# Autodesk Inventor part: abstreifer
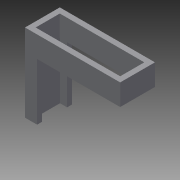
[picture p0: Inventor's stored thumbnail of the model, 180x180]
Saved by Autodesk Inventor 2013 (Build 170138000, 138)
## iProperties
Created: 2012-11
Part Number: abstreifer
Material: Allgemein
Document SubType Name: Modeling
Designer: otto
Density: 1 g/cm^3
Mass: 571.291 g
Surface Area: 1347.68 cm^2
Volume: 571.291 cm^3
Author: otto
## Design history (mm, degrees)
sketch "Skizze1"
  geometry: L1 (-119, -34)-(119, -34) reference; L2 (119, -34)-(119, 34) reference; L3 (119, 34)-(-119, 34) reference; L4 (-119, 34)-(-119, -34) reference; L5 (-129, 44)-(129, 44); L6 (129, 44)-(129, -44); L7 (129, -44)-(-129, -44); L8 (-129, -44)-(-129, 44); 1 further point
  constraints: 8 end point, 2 parallel, 1 horizontal, 1 perpendicular
  dimensions: "d0" = 10 distance between parallel lines of L3 L5; "d1" = 10 distance between parallel lines of L7 L1; "d2" = 10 distance between parallel lines of L4 L8; "d3" = 10 distance between parallel lines of L6 L2
extrude "Extrusion1" new body sketch "Skizze1" distance "d4" = 60; taper "d5" = 0 deg
sketch "Skizze2"
  geometry: L1 (129, 44)-(-129, 44) reference; L2 (-129, -44)-(129, -44) reference; L3 (-120, 35.5)-(120, 35.5) reference; L4 (-120, -35.5)-(120, -35.5) reference; L5 (120, 35.5)-(100, 35.5); L6 (100, 35.5)-(100, 44); L7 (100, 44)-(120, 44); L8 (120, 44)-(120, 35.5); L9 (120, -35.5)-(100, -35.5); L10 (100, -35.5)-(100, -44); L11 (100, -44)-(120, -44); L12 (120, -44)-(120, -35.5); 1 further point
  constraints: 16 end point, 4 parallel, 2 horizontal, 2 perpendicular, 2 point on line
  dimensions: "d6" = 20 distance of L6.end L7.end; "d7" = 20 distance of L11.end L10.end
extrude "Extrusion2" join sketch "Skizze2" distance "d8" = 160; taper "d9" = 0 deg
sketch "Skizze3"
  geometry: L1 (129, -44)-(129, 44) reference; L2 (129, 44)-(120, 44) reference; L3 (120, 44)-(129, 44); L4 (129, 44)-(129, -44); L5 (129, -44)-(120, -44); L6 (120, -44)-(120, 44); 1 further point
  constraints: 8 end point, 2 parallel, 1 horizontal, 1 perpendicular
extrude "Extrusion3" join sketch "Skizze3" distance "d10" = 160; taper "d11" = 0 deg
chamfer "Fase1" distance "d12" = 11; stored, may be unused: second distance "d13" = 2, angle "d14" = 45 deg
chamfer "Fase2" distance "d15" = 11; stored, may be unused: second distance "d16" = 2, angle "d17" = 45 deg
node "Volumenkörper1"
node "Referenz1"
node "Referenz2"
node "Referenz3"
